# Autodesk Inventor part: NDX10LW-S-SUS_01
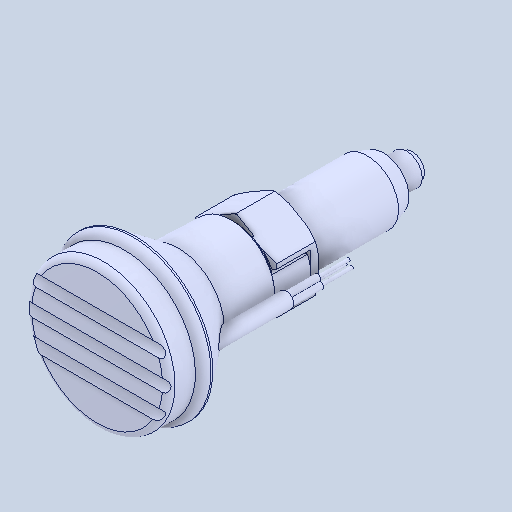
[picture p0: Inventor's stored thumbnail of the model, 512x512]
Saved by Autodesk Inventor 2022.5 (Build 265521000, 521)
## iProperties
Created: 2024-05
Part Number: NDX10LW-S-SUS_01
Material: 一般
Document SubType Name: Modeling
Designer: ImaoCorp
Density: 1 g/cm^3
Appearance: 既定
Author: ImaoCorp
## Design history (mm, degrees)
feature "NDX10LW-S-SUS_01"
node "ソリッド1"
